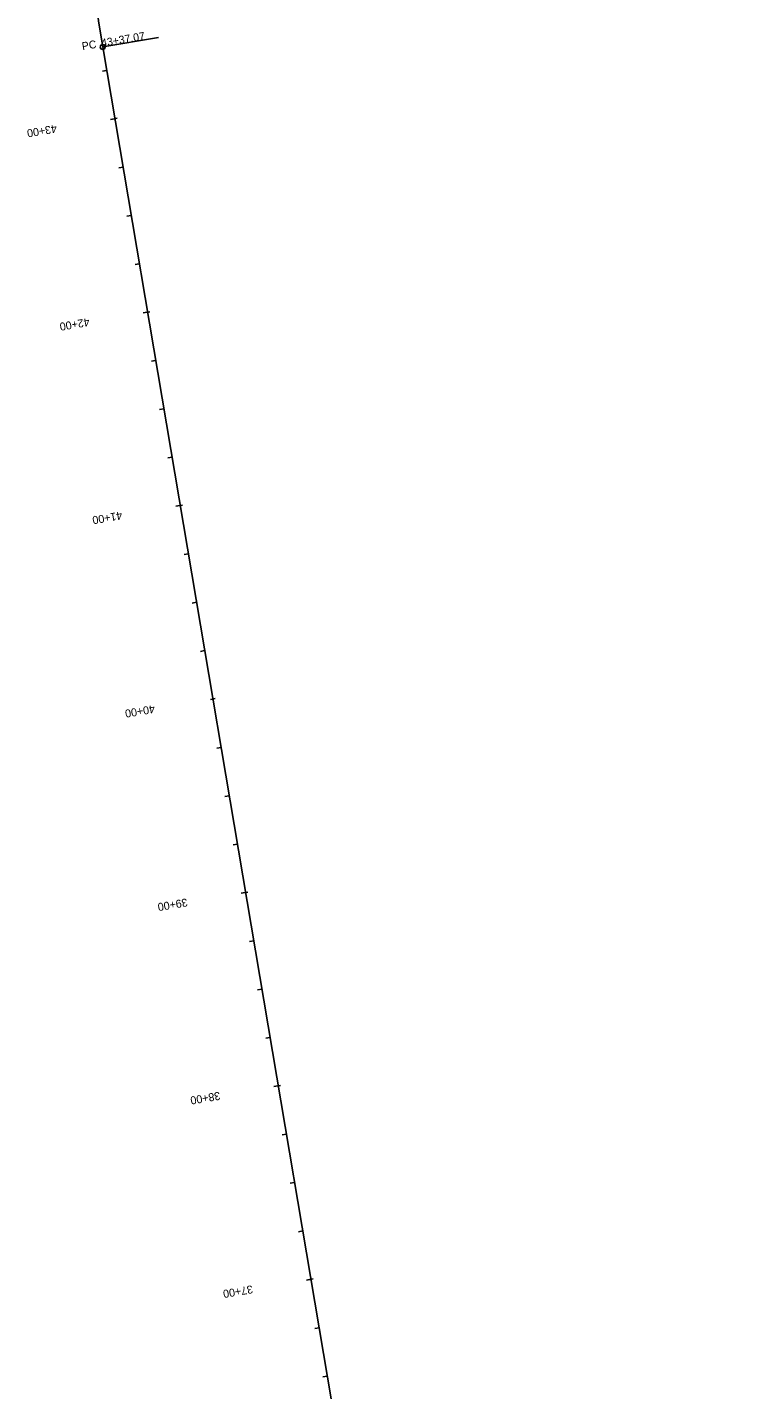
# Model space of a CAD drawing. Extents: x 21487884 to 21488802, y 8074558 to 8076894.
# Drawn here: x 21487951 to 21488310, y 8075303 to 8075997 of the extents above; entities that cross this region are included whole.
import ezdxf

# ---------------------------------------------------------------- set-up
doc = ezdxf.new("R2010")
doc.units = 0
for name, color, linetype in [('PS_BOLT', 7, 'Continuous'), ('PS_DIM', 7, 'Continuous'), ('PS_MID', 7, 'Continuous'), ('PS_SHAPE', 7, 'Continuous')]:
    doc.layers.add(name, color=color, linetype=linetype)

msp = doc.modelspace()

# ---------------------------------------------------------------- linework, layer by layer
at = {"layer": 'PS_BOLT'}
for p, q in [((21487995.28, 8075950.6), (21487993.13, 8075950.24)), ((21488011.94, 8075852), (21488009.78, 8075851.64)), ((21488028.59, 8075753.4), (21488026.44, 8075753.03)), ((21488044.04, 8075654.59), (21488046.45, 8075655)), ((21488061.9, 8075556.19), (21488059.75, 8075555.83)), ((21488078.56, 8075457.59), (21488076.4, 8075457.22)), ((21488095.21, 8075358.98), (21488093.06, 8075358.62))]:
    msp.add_line(p, q, dxfattribs=at)
at = {"layer": 'PS_DIM'}
msp.add_line((21487989.11, 8075987.15), (21488017.51, 8075991.95), dxfattribs=at)
msp.add_circle((21487989.11, 8075987.15), 1.25, dxfattribs=at)
at = {"layer": 'PS_MID'}
for p, q in [((21487991.12, 8075975.25), (21487988.97, 8075974.89)), ((21487994.08, 8075950.4), (21487996.49, 8075950.81)), ((21487999.45, 8075925.95), (21487997.29, 8075925.59)), ((21488003.61, 8075901.3), (21488001.46, 8075900.94)), ((21488007.77, 8075876.65), (21488005.62, 8075876.29)), ((21488010.73, 8075851.8), (21488013.14, 8075852.2)), ((21488016.1, 8075827.35), (21488013.95, 8075826.99)), ((21488020.27, 8075802.7), (21488018.11, 8075802.33)), ((21488024.43, 8075778.05), (21488022.28, 8075777.68)), ((21488027.39, 8075753.19), (21488029.8, 8075753.6)), ((21488032.76, 8075728.75), (21488030.6, 8075728.38)), ((21488036.92, 8075704.1), (21488034.77, 8075703.73)), ((21488041.08, 8075679.44), (21488038.93, 8075679.08)), ((21488044.04, 8075654.59), (21488046.45, 8075655)), ((21488049.41, 8075630.14), (21488047.26, 8075629.78)), ((21488053.57, 8075605.49), (21488051.42, 8075605.13)), ((21488057.74, 8075580.84), (21488055.58, 8075580.48)), ((21488060.7, 8075555.99), (21488063.11, 8075556.39)), ((21488066.07, 8075531.54), (21488063.91, 8075531.18)), ((21488070.23, 8075506.89), (21488068.08, 8075506.52)), ((21488074.39, 8075482.24), (21488072.24, 8075481.87)), ((21488077.35, 8075457.38), (21488079.76, 8075457.79)), ((21488082.72, 8075432.94), (21488080.57, 8075432.57)), ((21488086.88, 8075408.29), (21488084.73, 8075407.92)), ((21488091.05, 8075383.63), (21488088.89, 8075383.27)), ((21488094, 8075358.78), (21488096.42, 8075359.19)), ((21488099.38, 8075334.33), (21488097.22, 8075333.97)), ((21488103.54, 8075309.68), (21488101.39, 8075309.32))]:
    msp.add_line(p, q, dxfattribs=at)
at = {"layer": 'PS_SHAPE'}
msp.add_line((21488105.84, 8075296.07), (21487989.11, 8075987.15), dxfattribs=at)
msp.add_line((21488105.84, 8075296.07), (21487989.11, 8075987.15), dxfattribs=at)
msp.add_arc((21488575.8, 8076086.25), 595, 116.50071, 189.58714, dxfattribs=at)

# ---------------------------------------------------------------- texts
at = {"layer": 'PS_BOLT'}
msp.add_text('40+00', height=4.08, rotation=189.58714, dxfattribs=at).set_placement((21488015.33, 8075651.81))
at = {"layer": 'PS_DIM'}
for s, p in [('PC', (21487978.84, 8075985.5)), ('43+37.07', (21487988.68, 8075987.16))]:
    msp.add_text(s, height=4.008, rotation=9.58714, dxfattribs=at).set_placement(p)
at = {"layer": 'PS_MID'}
for s, p in [('43+00', (21487965.36, 8075947.62)), ('42+00', (21487982.02, 8075849.02)), ('41+00', (21487998.67, 8075750.41)), ('40+00', (21488015.33, 8075651.81)), ('39+00', (21488031.98, 8075553.21)), ('38+00', (21488048.64, 8075454.6)), ('37+00', (21488065.29, 8075356))]:
    msp.add_text(s, height=4.08, rotation=189.58714, dxfattribs=at).set_placement(p)

doc.saveas('drawing.dxf')
